Omron CX-Programmer project NuevoProyecto (CX-Programmer 9.50)

# PLC NewPLC1: CP1L-E EM

## Global symbols (name address type ; comment)
15.00 BOOL  ; CNT<3
15.01 BOOL  ; CNT=3

## Program P9_2 (cyclic task 0)
Local symbols
CNT 15.00 BOOL  ; Salida contador
DN1 0.01 BOOL  ; Detector de nivel inferior depósito A
DN2 0.02 BOOL  ; Detector de nivel superior depósito A
DN3 0.03 BOOL  ; Detector de nivel inferior depósito B
DN4 0.04 BOOL  ; Detector de nivel superior depósito B
Etapa_0 10.00 BOOL
Etapa_1 10.01 BOOL
Etapa_10 10.10 BOOL
Etapa_11 10.11 BOOL
Etapa_2 10.02 BOOL
Etapa_3 10.03 BOOL
Etapa_4 10.04 BOOL
Etapa_5 10.05 BOOL
Etapa_6 10.06 BOOL
Etapa_7 10.07 BOOL
Etapa_8 10.08 BOOL
Etapa_9 10.09 BOOL
F1 0.05 BOOL  ; Final carrera izquierda
F2 0.06 BOOL  ; Final carrera derecha
KVD 100.05 BOOL  ; Contactor Vagoneta para giro a Derechas
KVI 100.06 BOOL  ; Contactor Vagoneta para giro a Izquierdas
PM 0.00 BOOL  ; Pulsador de marcha
Salidas_deco 101 CHANNEL  ; Salidas para el decodificador (solo se usaran los dos bits de menos peso ya que la cuenta es hasta 3)
VA1 100.00 BOOL  ; Válvula llenado depósito A
VA2 100.02 BOOL  ; Válvula vaciado depósito A
VB1 100.01 BOOL  ; Válvula llenado depósito B
VB2 100.03 BOOL  ; Válvula vaciado depósito B
VC 100.04 BOOL  ; Válvula vaciado depósito C (vagoneta)

### Section Sección1_Programa_principal
; Programa principal (Etapas 0 ... 11)

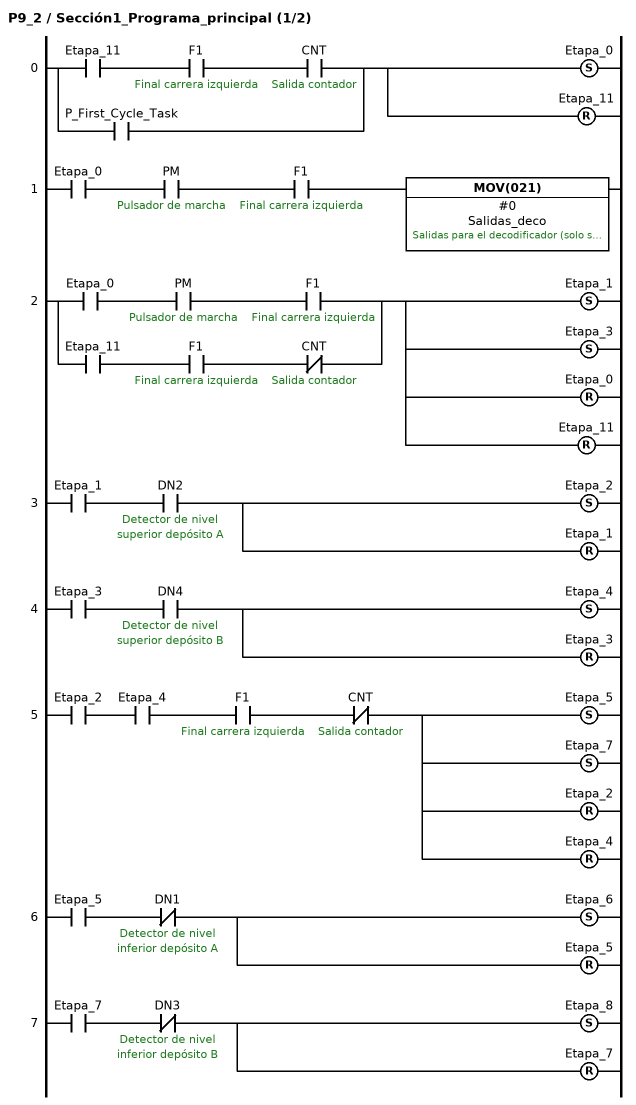
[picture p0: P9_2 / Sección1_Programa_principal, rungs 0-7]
; rung 0
LD Etapa_11
AND F1  ; Final carrera izquierda
AND CNT  ; Salida contador  // Cuando la vagoneta se vacíe 3 veces, la variable CNT pasará a 1  (ver Sección3_Contador_y_Salidas_deco)
OR P_First_Cycle_Task
SET Etapa_0
RSET Etapa_11
; rung 1
LD Etapa_0
AND PM  ; Pulsador de marcha
AND F1  ; Final carrera izquierda
MOV(021) #0 Salidas_deco  ; Salidas para el decodificador (solo se usaran los dos bits de menos peso ya que la cuenta es hasta 3)  // El display se reseteará al activar PM, Siempre y cuando se hayan realizado los tres viajes y esté en F1
; rung 2
LD Etapa_0
AND PM  ; Pulsador de marcha
AND F1  ; Final carrera izquierda
LD Etapa_11
AND F1  ; Final carrera izquierda
ANDNOT CNT  ; Salida contador
ORLD
SET Etapa_1
SET Etapa_3
RSET Etapa_0
RSET Etapa_11
; rung 3
LD Etapa_1
AND DN2  ; Detector de nivel superior depósito A
SET Etapa_2
RSET Etapa_1
; rung 4
LD Etapa_3
AND DN4  ; Detector de nivel superior depósito B
SET Etapa_4
RSET Etapa_3
; rung 5
LD Etapa_2
AND Etapa_4
AND F1  ; Final carrera izquierda
ANDNOT CNT  ; Salida contador
SET Etapa_5
SET Etapa_7
RSET Etapa_2
RSET Etapa_4
; rung 6
LD Etapa_5
ANDNOT DN1  ; Detector de nivel inferior depósito A
SET Etapa_6
RSET Etapa_5
; rung 7
LD Etapa_7
ANDNOT DN3  ; Detector de nivel inferior depósito B
SET Etapa_8
RSET Etapa_7

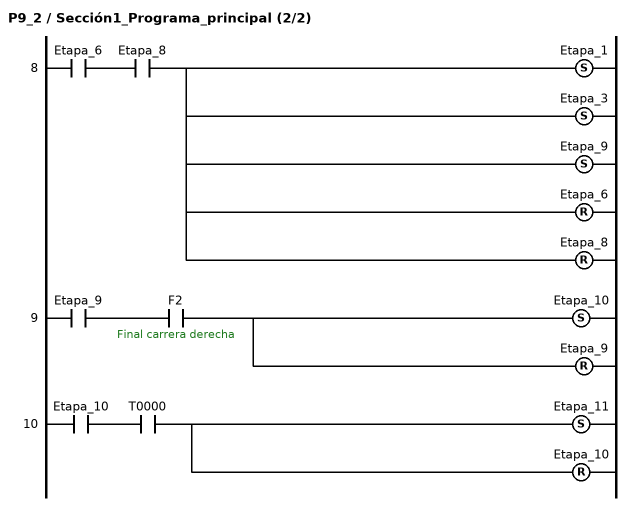
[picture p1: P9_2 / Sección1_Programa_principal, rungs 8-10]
; rung 8
LD Etapa_6
AND Etapa_8
SET Etapa_1
SET Etapa_3
SET Etapa_9
RSET Etapa_6
RSET Etapa_8
; rung 9
LD Etapa_9
AND F2  ; Final carrera derecha
SET Etapa_10
RSET Etapa_9
; rung 10
LD Etapa_10
AND T0000
SET Etapa_11
RSET Etapa_10

### Section Sección2_Temporizador

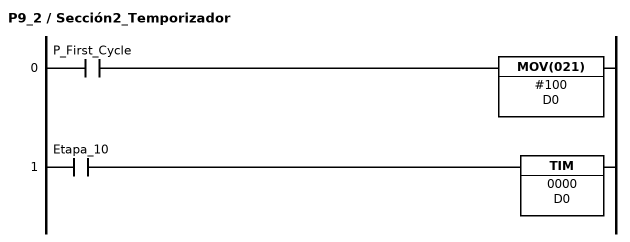
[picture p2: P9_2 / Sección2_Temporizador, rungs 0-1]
; rung 0
LD P_First_Cycle
MOV(021) #100 D0
; rung 1
LD Etapa_10
TIM 0000 D0

### Section Sección3_Contador_y_Salidas_deco
; Contador ascendente realizado mediante @++, CMP, KEEP y MOV (reset contador en Sección1)

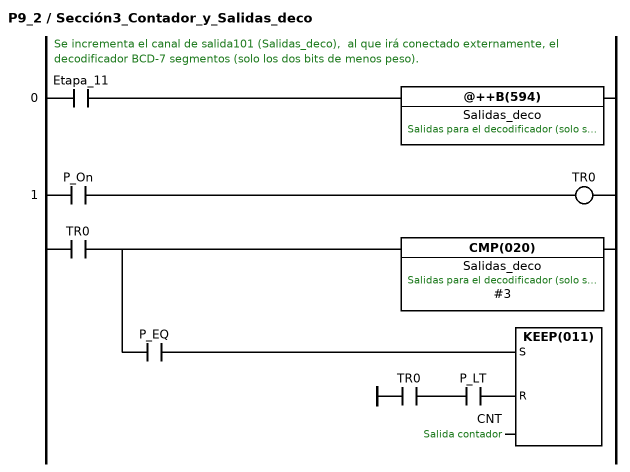
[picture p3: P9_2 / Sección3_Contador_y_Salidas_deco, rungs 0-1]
; rung 0: Se incrementa el canal de salida101 (Salidas_deco),  al que irá conectado externamente, el decodificador BCD-7 segmentos (solo los dos bits de menos peso).
LD Etapa_11
@++B(594) Salidas_deco  ; Salidas para el decodificador (solo se usaran los dos bits de menos peso ya que la cuenta es hasta 3)
; rung 1
LD P_On
OUT TR0
CMP(020) Salidas_deco #3  ; Salidas para el decodificador (solo se usaran los dos bits de menos peso ya que la cuenta es hasta 3)
AND P_EQ
LD TR0
AND P_LT
KEEP(011) CNT  ; Salida contador

### Section Sección4_Salidas_automatismo
; Salidas

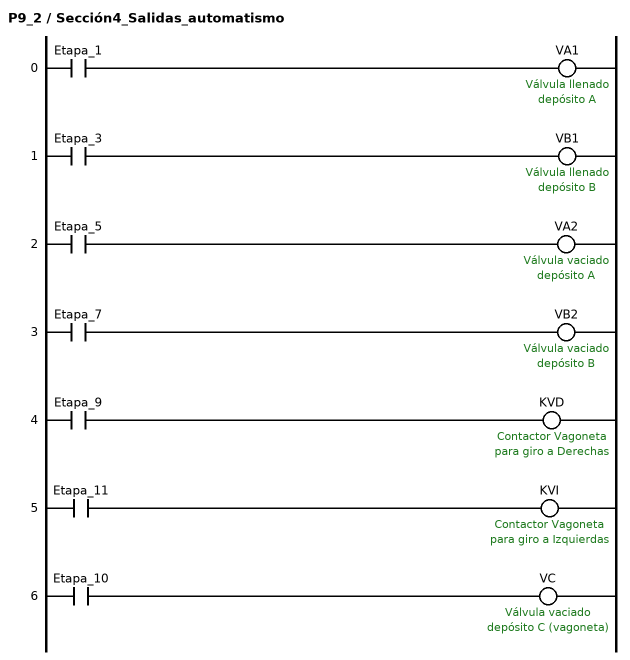
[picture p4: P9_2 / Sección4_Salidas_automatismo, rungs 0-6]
; rung 0
LD Etapa_1
OUT VA1  ; Válvula llenado depósito A
; rung 1
LD Etapa_3
OUT VB1  ; Válvula llenado depósito B
; rung 2
LD Etapa_5
OUT VA2  ; Válvula vaciado depósito A
; rung 3
LD Etapa_7
OUT VB2  ; Válvula vaciado depósito B
; rung 4
LD Etapa_9
OUT KVD  ; Contactor Vagoneta para giro a Derechas
; rung 5
LD Etapa_11
OUT KVI  ; Contactor Vagoneta para giro a Izquierdas
; rung 6
LD Etapa_10
OUT VC  ; Válvula vaciado depósito C (vagoneta)

### Section Sección5_Salidas_display_CX_designer

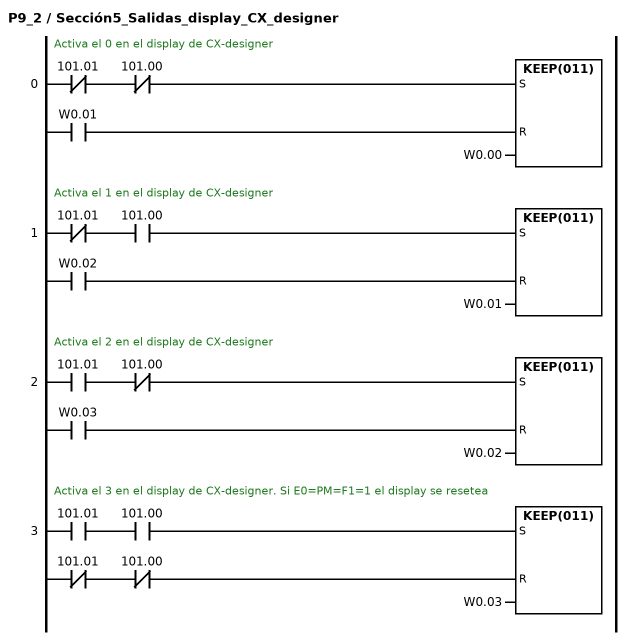
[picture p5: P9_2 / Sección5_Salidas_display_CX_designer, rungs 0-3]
; rung 0: Activa el 0 en el display de CX-designer
LDNOT 101.01
ANDNOT 101.00
LD W0.01
KEEP(011) W0.00
; rung 1: Activa el 1 en el display de CX-designer
LDNOT 101.01
AND 101.00
LD W0.02
KEEP(011) W0.01
; rung 2: Activa el 2 en el display de CX-designer
LD 101.01
ANDNOT 101.00
LD W0.03
KEEP(011) W0.02
; rung 3: Activa el 3 en el display de CX-designer. Si E0=PM=F1=1 el display se resetea
LD 101.01
AND 101.00
LDNOT 101.01
ANDNOT 101.00
KEEP(011) W0.03

### Section Sección6_END
; rung 0
END(001)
